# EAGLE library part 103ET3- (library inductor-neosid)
FILTER triple helix bandpass filter with 3 tab, type E
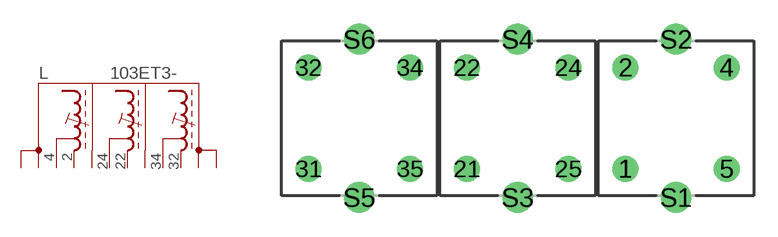
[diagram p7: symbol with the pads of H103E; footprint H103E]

Designator prefix L

## 103ET3-4224223432 (OC_FARNELL: unknown; OC_NEWARK: unknown)  [H103E]
2  GND1  pas
4  IN  pas
22  GND2  pas
24  Z  pas
32  GND3  pas
34  OUT1  pas
S1  S1  pas
S2  S2  pas
S3  S3  pas
S4  S4  pas
S5  S5  pas
S6  S6  pas

## Footprint H103E (pad centres in mm)
TRIPLE RF COIL ASSEMBLY 10.1, 4 pads, grid 2.5, 10 x 10 x 15 mm
drill 1.1 round: 1 6.8,-3.45; 2 6.8,2.95; 4 13.2,2.95; 5 13.2,-3.45; 21 -3.2,-3.45; 22 -3.2,2.95; 24 3.2,2.95; 25 3.2,-3.45; 31 -13.2,-3.45; 32 -13.2,2.95; 34 -6.8,2.95; 35 -6.8,-3.45
drill 1.3 round: S1 10,-5.25; S2 10,4.75; S3 0,-5.25; S4 0,4.75; S5 -10,-5.25; S6 -10,4.75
